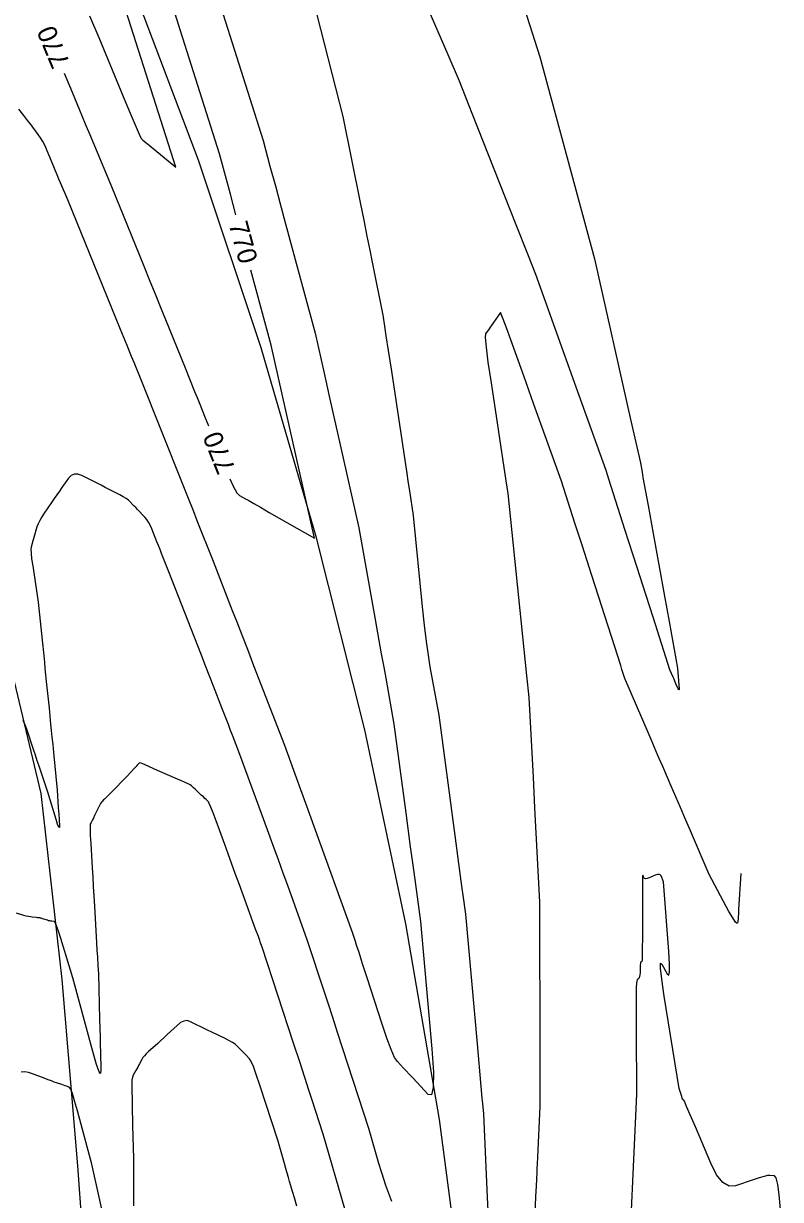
# Model space of a CAD drawing. Extents: x -26 to 1809989, y -25 to 828749.
# Drawn here: x 1809781.9 to 1809980.5, y 827895.2 to 828203.8 of the extents above; entities that cross this region are included whole.
import ezdxf

# ---------------------------------------------------------------- set-up
doc = ezdxf.new("R2010")
doc.units = 0
for name, color, linetype in [('DESIGN - CONTOURS - Index with Text', 7, 'Continuous'), ('DESIGN - CONTOURS - Intermediate with optional Text', 7, 'Continuous'), ('DESIGN - ROW - Slope Lines', 7, 'Continuous')]:
    doc.layers.add(name, color=color, linetype=linetype)

msp = doc.modelspace()

# ---------------------------------------------------------------- linework, layer by layer
at = {"layer": 'DESIGN - CONTOURS - Index with Text'}
for points in [[(1809837.62, 828153.6), (1809836.87, 828156.35), (1809836.16, 828159), (1809833.3, 828169.6), (1809823.06, 828201.85), (1809821.12, 828207.97), (1809819.69, 828212.48), (1809818.76, 828215.4), (1809818.35, 828216.71), (1809817.58, 828219.13), (1809815.38, 828225.13), (1809814.87, 828226.55), (1809814.26, 828228.22), (1809813.55, 828230.15), (1809812.75, 828232.34), (1809810.49, 828238.51), (1809809.58, 828241), (1809808.54, 828243.84), (1809807.37, 828247.04), (1809806.77, 828248.68)], [(1809792.55, 828190.77), (1809794.62, 828185.83), (1809796.48, 828181.36), (1809798.09, 828177.51), (1809799.43, 828174.29), (1809800.52, 828171.69), (1809804.96, 828161.01), (1809813.34, 828140.42), (1809815.05, 828136.22), (1809816.59, 828132.44), (1809817.96, 828129.08), (1809819.15, 828126.15), (1809824.34, 828113.43), (1809826.79, 828107.28), (1809827.43, 828105.68), (1809828.29, 828103.5), (1809829.38, 828100.76), (1809830.39, 828098.21)], [(1809835.99, 828084.29), (1809836.95, 828082.25), (1809837.86, 828080.7), (1809838.55, 828079.97), (1809840.13, 828079.1), (1809840.97, 828078.64), (1809842.29, 828077.89), (1809844.09, 828076.86), (1809846.38, 828075.54), (1809858.19, 828068.75), (1809846.85, 828119.44), (1809841.53, 828139.12)]]:
    msp.add_lwpolyline(points, dxfattribs=at)
at = {"layer": 'DESIGN - CONTOURS - Intermediate with optional Text'}
for points in [[(1809903.88, 828237.35), (1809917.31, 828195.06), (1809931.66, 828142.08), (1809941.23, 828099.58), (1809943.04, 828091.55), (1809943.72, 828088.56), (1809944.16, 828086.12), (1809944.41, 828084.7), (1809945.74, 828077.35), (1809947.07, 828070), (1809950.03, 828053.56), (1809951.24, 828046.88), (1809953.45, 828034.61), (1809953.85, 828030.2), (1809953.9, 828029.43), (1809953.88, 828029.02), (1809953.78, 828028.97), (1809953.61, 828029.27), (1809953.06, 828030.55), (1809952.66, 828031.48), (1809952.47, 828031.91), (1809952.3, 828032.33), (1809951.48, 828034.22), (1809947.13, 828047.78), (1809945.14, 828054.01), (1809942.88, 828061.05), (1809939.69, 828071), (1809935.43, 828084.27), (1809934.72, 828086.48), (1809926.89, 828108.36), (1809921.37, 828123.81), (1809916.3, 828137.98), (1809914.21, 828143.27), (1809911.16, 828150.98), (1809899.61, 828180.21), (1809896.26, 828188.68), (1809893.26, 828195.62), (1809874.64, 828238.52)], [(1809799.23, 828205.85), (1809801.62, 828200.1), (1809808.66, 828183.19), (1809810.4, 828179.03), (1809811.68, 828176.03), (1809812.5, 828174.19), (1809812.86, 828173.51), (1809813.2, 828173.24), (1809814.02, 828172.57), (1809814.85, 828171.88), (1809821.84, 828166.13), (1809806.24, 828215.28)], [(1809857.91, 828209.88), (1809865.64, 828179.4), (1809870.22, 828156.8), (1809871.16, 828152.19), (1809872, 828148.05), (1809872.74, 828144.37), (1809873.39, 828141.16), (1809876.18, 828127.27), (1809876.25, 828126.83), (1809876.27, 828126.71), (1809876.29, 828126.55), (1809876.32, 828126.35), (1809876.36, 828126.1), (1809876.62, 828124.37), (1809876.99, 828121.9), (1809877.59, 828117.97), (1809878.4, 828112.58), (1809880.86, 828096.24), (1809882.35, 828086.36), (1809882.83, 828083.2), (1809883.13, 828081.22), (1809884.1, 828074.75), (1809886.52, 828050.75), (1809887.03, 828045.91), (1809887.54, 828041.67), (1809888.04, 828038.04), (1809888.53, 828035.01), (1809890.81, 828022.28), (1809895.05, 827990.74), (1809896.49, 827980.07), (1809896.92, 827976.87), (1809897.16, 827975.09), (1809897.83, 827970.1), (1809900.88, 827936.11), (1809901.89, 827924.9), (1809902.17, 827921.81), (1809902.3, 827920.4), (1809902.54, 827917.72), (1809903.56, 827895.75), (1809903.97, 827887.09)], [(1809834.26, 828206.14), (1809844.75, 828173.07), (1809846.55, 828166.41), (1809847.96, 828161.19), (1809849.15, 828156.81), (1809850.65, 828151.25), (1809858.42, 828122.53), (1809860.76, 828112.07), (1809862.12, 828106), (1809863.07, 828101.78), (1809864.19, 828096.75), (1809869.85, 828071.46), (1809874.15, 828047.45), (1809875.76, 828038.44), (1809876.39, 828034.9), (1809876.91, 828032), (1809879.06, 828019.97), (1809882.18, 827996.68), (1809883.37, 827987.8), (1809883.86, 827984.2), (1809884.27, 827981.14), (1809886, 827968.18), (1809888.99, 827934.74), (1809889.42, 827928.62), (1809889.4, 827924.59), (1809888.94, 827922.65), (1809888.05, 827922.81), (1809885.07, 827926.01), (1809884.02, 827927.14), (1809883.09, 827928.13), (1809882.29, 827928.98), (1809881.61, 827929.69), (1809879.98, 827931.41), (1809879.26, 827932.52), (1809878.35, 827934.56), (1809877.23, 827937.55), (1809875.91, 827941.47), (1809872.13, 827953.17), (1809870.86, 827957.08), (1809869.92, 827960.01), (1809869.28, 827961.97), (1809868.96, 827962.95), (1809868.19, 827965.29), (1809858.15, 827993.09), (1809856.2, 827998.47), (1809854.66, 828002.72), (1809853.54, 828005.83), (1809852.82, 828007.8), (1809850.43, 828014.34), (1809842.36, 828035.24), (1809840.71, 828039.51), (1809839.23, 828043.34), (1809837.91, 828046.75), (1809836.75, 828049.73), (1809831.73, 828062.63), (1809827.49, 828073.34), (1809826.45, 828075.95), (1809825.15, 828079.21), (1809823.6, 828083.11), (1809812.75, 828110.33), (1809810.92, 828114.82), (1809810.26, 828116.43), (1809809.08, 828119.33), (1809807.37, 828123.51), (1809793.48, 828157.53), (1809791.61, 828162), (1809791.19, 828163.01), (1809790.73, 828164.13), (1809790.21, 828165.35), (1809789.66, 828166.68), (1809788.11, 828170.38), (1809787.53, 828171.68), (1809786.95, 828172.84), (1809786.36, 828173.85), (1809785.77, 828174.71), (1809783.6, 828177.56), (1809783.04, 828178.29), (1809782.51, 828178.98), (1809782, 828179.64), (1809780.69, 828181.35)], [(1809970.1, 827980.76), (1809969.49, 827971.36), (1809969.43, 827970.4), (1809969.27, 827967.96), (1809969.1, 827967.66), (1809968.66, 827968.04), (1809967.95, 827969.1), (1809966.97, 827970.83), (1809961.79, 827980.49), (1809956.86, 827991.98), (1809955.15, 827995.97), (1809954.24, 827998.09), (1809951.82, 828003.7), (1809949.61, 828008.84), (1809948.69, 828010.97), (1809948.35, 828011.76), (1809946.55, 828015.93), (1809945.76, 828017.77), (1809939.67, 828031.9), (1809939.14, 828033.53), (1809938.89, 828034.34), (1809938.56, 828035.34), (1809936.13, 828042.93), (1809930.98, 828058.96), (1809928.43, 828066.91), (1809926.56, 828072.71), (1809923, 828083.76), (1809917.97, 828097.79), (1809915.7, 828104.12), (1809913.2, 828111.08), (1809909.72, 828120.79), (1809908.58, 828123.97), (1809907.74, 828126.22), (1809907.23, 828127.55), (1809907.02, 828127.95), (1809906.91, 828127.8), (1809906.83, 828127.68), (1809906.43, 828127.12), (1809904.59, 828124.49), (1809904.42, 828124.24), (1809904.31, 828124.1), (1809904.04, 828123.72), (1809903.06, 828122.39), (1809903.01, 828121.38), (1809903.24, 828118.9), (1809903.75, 828114.94), (1809904.55, 828109.51), (1809908.46, 828083.79), (1809908.96, 828080.51), (1809913.86, 828032.69), (1809914.45, 828026.94), (1809915.56, 828006.08), (1809915.98, 827998.02), (1809917.26, 827973.26), (1809917.29, 827958.53), (1809917.33, 827947.04), (1809917.34, 827944.39), (1809917.34, 827941.26), (1809917.35, 827937.65), (1809917.36, 827919.62), (1809916.73, 827906.36), (1809916.65, 827904.62), (1809916.59, 827903.3), (1809916.55, 827902.4), (1809916.46, 827900.57), (1809916.37, 827898.72), (1809916.31, 827897.43), (1809916.24, 827895.9), (1809916.04, 827891.51)], [(1809878.49, 827894.68), (1809876.99, 827898.89), (1809875.86, 827902.21), (1809875.11, 827904.63), (1809872.45, 827913.86), (1809865.68, 827934.76), (1809864.3, 827939.05), (1809863.03, 827942.96), (1809861.88, 827946.48), (1809860.86, 827949.62), (1809856.35, 827963.37), (1809851.2, 827977.63), (1809850.04, 827980.83), (1809848.76, 827984.33), (1809847.38, 827988.13), (1809845.89, 827992.22), (1809838.66, 828012.02), (1809836.71, 828017.07), (1809836.23, 828018.3), (1809835.64, 828019.83), (1809834.09, 828023.8), (1809831.72, 828029.9), (1809830.76, 828032.37), (1809829.65, 828035.23), (1809828.39, 828038.48), (1809820.04, 828059.92), (1809818.11, 828064.78), (1809817.7, 828065.81), (1809817.3, 828066.81), (1809816.91, 828067.79), (1809815.52, 828071.25), (1809815.13, 828072.15), (1809814.69, 828072.95), (1809814.22, 828073.65), (1809813.71, 828074.26), (1809811.79, 828076.3), (1809811.34, 828076.77), (1809810.95, 828077.18), (1809810.61, 828077.53), (1809809.8, 828078.38), (1809809.4, 828078.72), (1809808.82, 828079.13), (1809808.07, 828079.59), (1809807.13, 828080.1), (1809804.39, 828081.55), (1809803.35, 828082.09), (1809802.29, 828082.64), (1809801.22, 828083.18), (1809800.13, 828083.73), (1809797.2, 828085.19), (1809796.16, 828085.56), (1809795.23, 828085.56), (1809794.41, 828085.2), (1809793.71, 828084.47), (1809791.98, 828082.05), (1809791.32, 828081.12), (1809790.65, 828080.16), (1809789.96, 828079.17), (1809789.24, 828078.14), (1809787.33, 828075.36), (1809786.67, 828074.35), (1809786.13, 828073.41), (1809785.72, 828072.54), (1809785.43, 828071.73), (1809784.62, 828068.95), (1809784.44, 828068.32), (1809784.29, 828067.8), (1809784.17, 828067.38), (1809783.88, 828066.38), (1809783.83, 828065.79), (1809783.88, 828064.79), (1809784.03, 828063.37), (1809784.3, 828061.53), (1809785.75, 828051.98), (1809786.77, 828041.98), (1809787.18, 828037.98), (1809787.36, 828036.2), (1809787.52, 828034.57), (1809787.95, 828030.4), (1809788.1, 828028.83), (1809788.42, 828025.7), (1809788.58, 828024.13), (1809789.01, 828019.93), (1809789.17, 828018.29), (1809789.35, 828016.51), (1809789.55, 828014.59), (1809789.75, 828012.53), (1809790.75, 828002.6), (1809791.02, 827998.12), (1809791.07, 827997.2), (1809791.12, 827996.36), (1809791.21, 827994.91), (1809791.31, 827993.18), (1809791.29, 827992.8), (1809791.13, 827992.97), (1809790.85, 827993.69), (1809790.45, 827994.95), (1809788.26, 828002.11), (1809786, 828008.91), (1809785.51, 828010.37), (1809785.03, 828011.83), (1809784.54, 828013.29), (1809782.75, 828018.65), (1809782.27, 828019.94), (1809781.81, 828020.91)], [(1809866.19, 827892.75), (1809860.54, 827912.33), (1809857.56, 827921.54), (1809856.78, 827923.95), (1809855.72, 827927.2), (1809854.38, 827931.31), (1809852.75, 827936.28), (1809844.5, 827961.45), (1809844.18, 827962.35), (1809844.09, 827962.59), (1809843.98, 827962.88), (1809843.86, 827963.22), (1809843.5, 827964.22), (1809842.78, 827966.18), (1809842.09, 827968.07), (1809841.18, 827970.58), (1809838.45, 827978.06), (1809837.45, 827980.81), (1809835.57, 827985.96), (1809834.69, 827988.36), (1809832.4, 827994.62), (1809831.63, 827996.69), (1809831.04, 827998.21), (1809830.63, 827999.18), (1809830.4, 827999.6), (1809830.01, 827999.97), (1809829.81, 828000.16), (1809829.5, 828000.46), (1809829.08, 828000.86), (1809828.54, 828001.36), (1809826.97, 828002.85), (1809826.43, 828003.35), (1809825.99, 828003.74), (1809825.65, 828004), (1809825.42, 828004.14), (1809824.93, 828004.37), (1809824.62, 828004.51), (1809824.09, 828004.74), (1809823.32, 828005.08), (1809822.31, 828005.51), (1809817.08, 828007.78), (1809813.82, 828009.28), (1809813.2, 828009.56), (1809812.74, 828009.72), (1809812.43, 828009.79), (1809812.27, 828009.76), (1809812.07, 828009.52), (1809811.74, 828009.16), (1809811.44, 828008.83), (1809811.05, 828008.4), (1809809.03, 828006.2), (1809804.94, 828002.09), (1809804.15, 828001.31), (1809803.55, 828000.71), (1809803.13, 828000.29), (1809802.9, 828000.06), (1809802.51, 827999.7), (1809802.34, 827999.49), (1809802.12, 827999.12), (1809801.84, 827998.61), (1809801.5, 827997.95), (1809800.55, 827995.99), (1809800.22, 827995.33), (1809799.97, 827994.81), (1809799.66, 827994.18), (1809799.42, 827993.71), (1809799.36, 827993.27), (1809799.36, 827992.27), (1809799.42, 827990.72), (1809799.53, 827988.62), (1809799.91, 827982.3), (1809800.05, 827979.89), (1809800.2, 827977.4), (1809800.35, 827974.82), (1809800.51, 827972.17), (1809801.07, 827962.58), (1809801.17, 827960.78), (1809801.25, 827959.58), (1809801.28, 827958.97), (1809801.33, 827958.14), (1809801.37, 827957.44), (1809801.4, 827957.04), (1809801.42, 827956.6), (1809801.55, 827954.47), (1809801.86, 827942.51), (1809801.98, 827937.8), (1809802.03, 827935.75), (1809802.08, 827933.91), (1809802.19, 827929.29), (1809802.09, 827928.29), (1809801.7, 827928.76), (1809801.02, 827930.69), (1809800.05, 827934.09), (1809794.85, 827953.39), (1809791.69, 827963.72), (1809791.07, 827965.66), (1809790.57, 827967.05), (1809790.17, 827967.89), (1809789.9, 827968.18), (1809789.3, 827968.22), (1809789.06, 827968.25), (1809788.79, 827968.31), (1809788.49, 827968.38), (1809788.16, 827968.49), (1809787.23, 827968.79), (1809786.91, 827968.9), (1809786.66, 827968.98), (1809786.48, 827969.03), (1809786.37, 827969.06), (1809786.17, 827969.1), (1809786.06, 827969.11), (1809785.86, 827969.14), (1809785.58, 827969.17), (1809785.23, 827969.2), (1809784.16, 827969.3), (1809783.73, 827969.36), (1809783.21, 827969.46), (1809782.62, 827969.6), (1809781.95, 827969.79), (1809780.06, 827970.36)], [(1809980.48, 827892.6), (1809980.13, 827896.45), (1809979.75, 827899.2), (1809979.34, 827900.87), (1809978.91, 827901.45), (1809977.73, 827901.54), (1809977.12, 827901.49), (1809976.19, 827901.29), (1809974.93, 827900.92), (1809973.35, 827900.4), (1809968.7, 827898.79), (1809966.99, 827898.71), (1809965.33, 827899.68), (1809963.74, 827901.69), (1809962.19, 827904.75), (1809958.16, 827914.29), (1809956.83, 827917.42), (1809955.87, 827919.65), (1809955.28, 827920.99), (1809955.05, 827921.42), (1809954.94, 827921.38), (1809954.88, 827921.42), (1809954.81, 827921.58), (1809954.7, 827921.85), (1809954.58, 827922.24), (1809953.93, 827924.32), (1809949.99, 827948.57), (1809949.32, 827953), (1809948.99, 827955.89), (1809949, 827957.23), (1809949.35, 827957.02), (1809950.75, 827954.43), (1809951.17, 827954.06), (1809951.39, 827954.92), (1809951.4, 827957), (1809951.21, 827960.3), (1809949.83, 827978.54), (1809949.15, 827980.12), (1809948.94, 827980.39), (1809948.62, 827980.51), (1809948.19, 827980.48), (1809947.64, 827980.31), (1809946.01, 827979.66), (1809945.47, 827979.47), (1809945.06, 827979.4), (1809944.78, 827979.44), (1809944.64, 827979.6), (1809944.45, 827980.17), (1809944.39, 827980.3), (1809944.34, 827980.27), (1809944.31, 827980.07), (1809944.3, 827979.71), (1809944.28, 827977.64), (1809944.26, 827963.76), (1809944.24, 827961.15), (1809944.21, 827959.27), (1809944.16, 827958.12), (1809944.09, 827957.7), (1809943.87, 827957.54), (1809943.8, 827957.42), (1809943.75, 827957.16), (1809943.7, 827956.77), (1809943.68, 827956.25), (1809943.64, 827954.68), (1809943.6, 827954.15), (1809943.54, 827953.73), (1809943.43, 827953.43), (1809943.3, 827953.23), (1809942.89, 827952.85), (1809942.76, 827952.55), (1809942.67, 827951.92), (1809942.62, 827950.97), (1809942.61, 827949.69), (1809942.64, 827944.21), (1809942.65, 827939.76), (1809942.71, 827922.88), (1809941.18, 827888.59)], [(1809853.63, 827893.46), (1809852.99, 827895.64), (1809852.56, 827897.08), (1809851.7, 827899.91), (1809851.37, 827901.01), (1809851.03, 827902.16), (1809850.69, 827903.38), (1809850.33, 827904.67), (1809848.64, 827910.81), (1809843.9, 827925.27), (1809842.97, 827928.03), (1809842.21, 827930.09), (1809841.62, 827931.47), (1809841.2, 827932.15), (1809840.3, 827933.07), (1809839.96, 827933.41), (1809839.61, 827933.77), (1809839.25, 827934.14), (1809838.88, 827934.53), (1809837.88, 827935.56), (1809837.39, 827935.98), (1809836.69, 827936.44), (1809835.78, 827936.96), (1809834.64, 827937.53), (1809831.33, 827939.11), (1809830.15, 827939.67), (1809829.11, 827940.18), (1809828.2, 827940.62), (1809827.42, 827941.01), (1809825.51, 827941.97), (1809824.76, 827942.17), (1809823.96, 827942.06), (1809823.09, 827941.63), (1809822.17, 827940.89), (1809819.62, 827938.5), (1809818.7, 827937.64), (1809817.86, 827936.87), (1809817.1, 827936.17), (1809816.41, 827935.55), (1809814.68, 827934.02), (1809814.08, 827933.46), (1809813.59, 827932.94), (1809813.21, 827932.45), (1809812.93, 827932), (1809812.32, 827930.85), (1809812.09, 827930.42), (1809811.85, 827929.98), (1809811.61, 827929.53), (1809811.36, 827929.08), (1809810.7, 827927.86), (1809810.48, 827927.31), (1809810.34, 827926.54), (1809810.27, 827925.57), (1809810.27, 827924.39), (1809810.36, 827920.97), (1809810.39, 827919.62), (1809810.43, 827918.12), (1809810.47, 827916.47), (1809810.52, 827914.67), (1809810.74, 827905.95), (1809810.77, 827896.1), (1809810.77, 827893.59)], [(1809806.99, 827872.25), (1809799.8, 827904.54), (1809796.03, 827918.51), (1809795.3, 827921.14), (1809794.71, 827923.04), (1809794.28, 827924.21), (1809793.99, 827924.65), (1809793.41, 827924.85), (1809793.15, 827924.94), (1809792.82, 827925.06), (1809792.42, 827925.2), (1809791.94, 827925.37), (1809790.56, 827925.84), (1809789.96, 827926.05), (1809789.22, 827926.33), (1809788.32, 827926.66), (1809787.28, 827927.07), (1809784.28, 827928.23), (1809783.2, 827928.57), (1809782.2, 827928.72), (1809781.27, 827928.68)]]:
    msp.add_lwpolyline(points, dxfattribs=at)
at = {"layer": 'DESIGN - ROW - Slope Lines'}
for p, q in [((1809827.77, 828167.92), (1809809.5, 828216.39)), ((1809844.2, 828118.73), (1809827.77, 828167.92)), ((1809858.77, 828068.89), (1809844.2, 828118.73)), ((1809871.44, 828018.47), (1809858.77, 828068.89)), ((1809786.54, 828001.77), (1809775.06, 828049.5)), ((1809882.19, 827967.56), (1809871.44, 828018.47)), ((1809792.06, 827952.93), (1809786.54, 828001.77)), ((1809890.99, 827916.24), (1809882.19, 827967.56)), ((1809796.11, 827904.07), (1809792.06, 827952.93)), ((1809897.86, 827864.4), (1809890.99, 827916.24)), ((1809799.83, 827855.42), (1809796.11, 827904.07))]:
    msp.add_line(p, q, dxfattribs=at)

# ---------------------------------------------------------------- texts
at = {"layer": 'DESIGN - CONTOURS - Index with Text'}
for rotation, p in [(112.6724, (1809794.15, 828193.43)), (285.1232, (1809835.68, 828151.17)), (111.9138, (1809837.59, 828086.92))]:
    msp.add_text('770', height=5, rotation=rotation, dxfattribs=at).set_placement(p)

doc.saveas('drawing.dxf')
